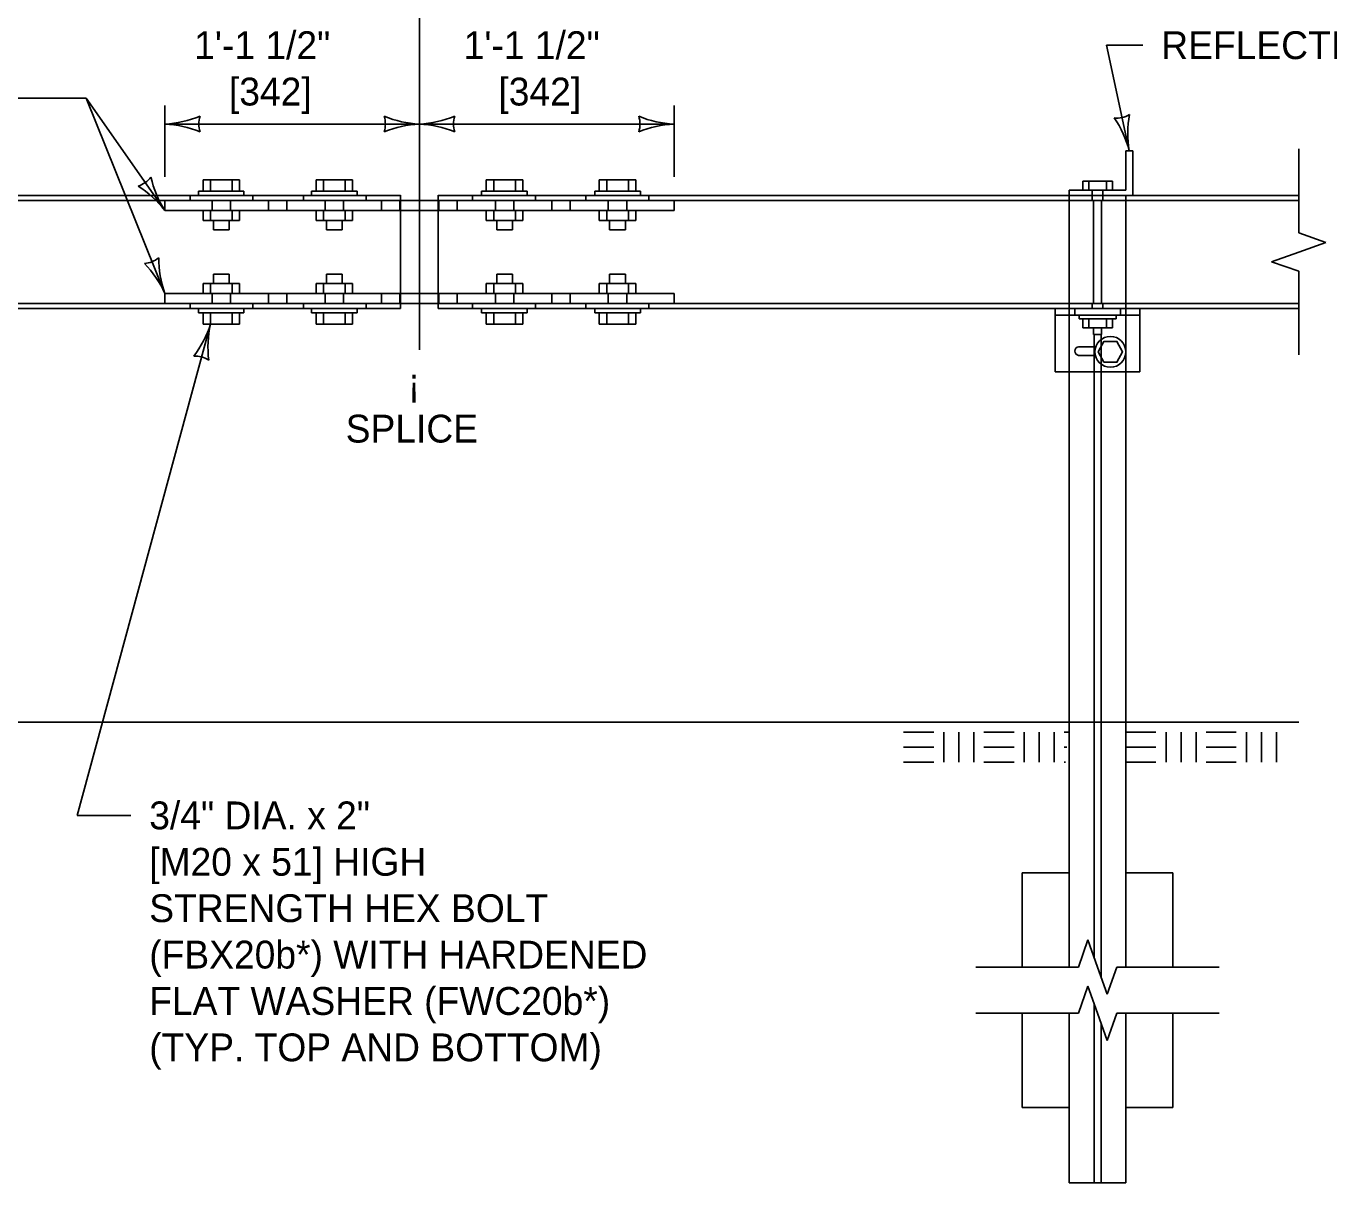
# Model space of a CAD drawing. Extents: x 49991.4 to 50021, y 49987.6 to 50011.4.
# Drawn here: x 50012.323 to 50015.133, y 50004.402 to 50006.896 of the extents above; entities that cross this region are included whole.
import ezdxf

# ---------------------------------------------------------------- set-up
doc = ezdxf.new("R2010")
doc.units = 0
for name, color, linetype in [('Level 1', 7, 'Continuous'), ('Level 2', 7, 'Continuous'), ('Level 3', 7, 'Continuous'), ('Level 4', 7, 'Continuous'), ('Level 5', 7, 'Continuous'), ('Level 6', 7, 'Continuous')]:
    doc.layers.add(name, color=color, linetype=linetype)

msp = doc.modelspace()

# ---------------------------------------------------------------- linework, layer by layer
at = {"layer": 'Level 1'}
for p, q in [((50014.695, 50006.5419), (50014.695, 50006.627)), ((50014.695, 50006.627), (50014.7102, 50006.627)), ((50014.7102, 50006.5309), (50014.7102, 50006.627)), ((50012.7049, 50006.5402), (50012.7049, 50006.5646)), ((50012.7049, 50006.5646), (50012.7838, 50006.5646)), ((50012.721, 50006.5402), (50012.721, 50006.5646)), ((50012.7677, 50006.5402), (50012.7677, 50006.5646)), ((50012.7838, 50006.5402), (50012.7838, 50006.5646)), ((50012.9486, 50006.5402), (50012.9486, 50006.5646)), ((50012.9486, 50006.5646), (50013.0274, 50006.5646)), ((50012.9646, 50006.5402), (50012.9646, 50006.5646)), ((50013.0114, 50006.5402), (50013.0114, 50006.5646)), ((50013.0274, 50006.5402), (50013.0274, 50006.5646)), ((50013.3158, 50006.5402), (50013.3158, 50006.5646)), ((50013.3946, 50006.5646), (50013.3158, 50006.5646)), ((50013.3318, 50006.5402), (50013.3318, 50006.5646)), ((50013.3786, 50006.5402), (50013.3786, 50006.5646)), ((50013.3946, 50006.5402), (50013.3946, 50006.5646)), ((50013.5594, 50006.5402), (50013.5594, 50006.5646)), ((50013.6383, 50006.5646), (50013.5594, 50006.5646)), ((50013.5755, 50006.5402), (50013.5755, 50006.5646)), ((50013.6222, 50006.5402), (50013.6222, 50006.5646)), ((50013.6383, 50006.5402), (50013.6383, 50006.5646)), ((50014.6026, 50006.5419), (50014.6026, 50006.5616)), ((50014.6026, 50006.5616), (50014.6665, 50006.5616)), ((50014.6156, 50006.5419), (50014.6156, 50006.5616)), ((50014.6534, 50006.5419), (50014.6534, 50006.5616)), ((50014.6665, 50006.5419), (50014.6665, 50006.5616)), ((50010.9506, 50006.5309), (50013.131, 50006.5309)), ((50012.6948, 50006.5402), (50012.7932, 50006.5402)), ((50012.6948, 50006.5309), (50012.6948, 50006.5402)), ((50012.7932, 50006.5309), (50012.7932, 50006.5402)), ((50012.9392, 50006.5402), (50013.0375, 50006.5402)), ((50012.9392, 50006.5309), (50012.9392, 50006.5402)), ((50013.0375, 50006.5309), (50013.0375, 50006.5402)), ((50013.131, 50006.287), (50013.131, 50006.5316)), ((50013.131, 50006.5198), (50013.2122, 50006.5198)), ((50013.1602, 50006.5199), (50013.183, 50006.5199)), ((50013.2122, 50006.287), (50013.2122, 50006.5316)), ((50013.2122, 50006.5309), (50015.0681, 50006.5309)), ((50013.404, 50006.5402), (50013.3057, 50006.5402)), ((50013.3057, 50006.5309), (50013.3057, 50006.5402)), ((50013.404, 50006.5309), (50013.404, 50006.5402)), ((50013.6484, 50006.5402), (50013.55, 50006.5402)), ((50013.55, 50006.5309), (50013.55, 50006.5402)), ((50013.6484, 50006.5309), (50013.6484, 50006.5402)), ((50014.5732, 50006.5309), (50014.5732, 50006.5419)), ((50014.5732, 50006.5419), (50014.695, 50006.5419)), ((50013.131, 50006.4983), (50013.2122, 50006.4983)), ((50013.131, 50006.3197), (50013.2122, 50006.3197)), ((50013.131, 50006.2981), (50013.2122, 50006.2981)), ((50013.1602, 50006.2981), (50013.183, 50006.2981)), ((50010.9506, 50006.287), (50013.131, 50006.287)), ((50012.6948, 50006.2871), (50012.6948, 50006.2778)), ((50012.6948, 50006.2778), (50012.7932, 50006.2778)), ((50012.7049, 50006.2778), (50012.7049, 50006.2534)), ((50012.721, 50006.2778), (50012.721, 50006.2534)), ((50012.7677, 50006.2778), (50012.7677, 50006.2534)), ((50012.7838, 50006.2778), (50012.7838, 50006.2534)), ((50012.7932, 50006.2871), (50012.7932, 50006.2778)), ((50012.9392, 50006.2871), (50012.9392, 50006.2778)), ((50012.9392, 50006.2778), (50013.0375, 50006.2778)), ((50012.9486, 50006.2778), (50012.9486, 50006.2534)), ((50012.9646, 50006.2778), (50012.9646, 50006.2534)), ((50013.0114, 50006.2778), (50013.0114, 50006.2534)), ((50013.0274, 50006.2778), (50013.0274, 50006.2534)), ((50013.0375, 50006.2871), (50013.0375, 50006.2778)), ((50013.2122, 50006.287), (50015.0681, 50006.287)), ((50013.3057, 50006.2871), (50013.3057, 50006.2778)), ((50013.404, 50006.2778), (50013.3057, 50006.2778)), ((50013.3158, 50006.2778), (50013.3158, 50006.2534)), ((50013.3318, 50006.2778), (50013.3318, 50006.2534)), ((50013.3786, 50006.2778), (50013.3786, 50006.2534)), ((50013.3946, 50006.2778), (50013.3946, 50006.2534)), ((50013.404, 50006.2871), (50013.404, 50006.2778)), ((50013.55, 50006.2871), (50013.55, 50006.2778)), ((50013.6484, 50006.2778), (50013.55, 50006.2778)), ((50013.5594, 50006.2778), (50013.5594, 50006.2534)), ((50013.5755, 50006.2778), (50013.5755, 50006.2534)), ((50013.6222, 50006.2778), (50013.6222, 50006.2534)), ((50013.6383, 50006.2778), (50013.6383, 50006.2534)), ((50013.6484, 50006.2871), (50013.6484, 50006.2778)), ((50014.5427, 50006.1508), (50014.5427, 50006.287)), ((50014.5427, 50006.2724), (50014.7256, 50006.2724)), ((50014.5943, 50006.2724), (50014.5943, 50006.2649)), ((50014.5943, 50006.2649), (50014.6741, 50006.2649)), ((50014.6026, 50006.2649), (50014.6026, 50006.2452)), ((50014.6156, 50006.2649), (50014.6156, 50006.2452)), ((50014.6534, 50006.2649), (50014.6534, 50006.2452)), ((50014.6665, 50006.2649), (50014.6665, 50006.2452)), ((50014.6741, 50006.2724), (50014.6741, 50006.2649)), ((50014.7256, 50006.1508), (50014.7256, 50006.287)), ((50012.7049, 50006.2534), (50012.7838, 50006.2534)), ((50012.9486, 50006.2534), (50013.0274, 50006.2534)), ((50013.3946, 50006.2534), (50013.3158, 50006.2534)), ((50013.6383, 50006.2534), (50013.5594, 50006.2534)), ((50014.6026, 50006.2452), (50014.6665, 50006.2452)), ((50014.5931, 50006.2045), (50014.6303, 50006.2045)), ((50014.5931, 50006.1859), (50014.6294, 50006.1859)), ((50014.5427, 50006.1508), (50014.7256, 50006.1508)), ((50014.5732, 50005.3957), (50014.5732, 50006.1508)), ((50014.695, 50005.3957), (50014.695, 50006.1508)), ((50015.0681, 50005.3957), (50010.756, 50005.3957)), ((50014.2157, 50005.3741), (50014.2807, 50005.3741)), ((50014.3024, 50005.3091), (50014.3024, 50005.3741)), ((50014.3349, 50005.3091), (50014.3349, 50005.3741)), ((50014.3674, 50005.3091), (50014.3674, 50005.3741)), ((50014.389, 50005.3741), (50014.4541, 50005.3741)), ((50014.4758, 50005.3091), (50014.4758, 50005.3741)), ((50014.5082, 50005.3091), (50014.5082, 50005.3741)), ((50014.5407, 50005.3091), (50014.5407, 50005.3741)), ((50014.6951, 50005.3741), (50014.6951, 50005.3741)), ((50014.6951, 50005.3741), (50014.7601, 50005.3741)), ((50014.7818, 50005.3091), (50014.7818, 50005.3741)), ((50014.8143, 50005.3091), (50014.8143, 50005.3741)), ((50014.8468, 50005.3091), (50014.8468, 50005.3741)), ((50014.8685, 50005.3741), (50014.9334, 50005.3741)), ((50014.9551, 50005.3091), (50014.9551, 50005.3741)), ((50014.9877, 50005.3091), (50014.9877, 50005.3741)), ((50015.0202, 50005.3091), (50015.0202, 50005.3741)), ((50014.2157, 50005.3416), (50014.2807, 50005.3416)), ((50014.389, 50005.3416), (50014.4541, 50005.3416)), ((50014.6951, 50005.3416), (50014.7601, 50005.3416)), ((50014.8685, 50005.3416), (50014.9334, 50005.3416)), ((50014.2157, 50005.3091), (50014.2807, 50005.3091)), ((50014.389, 50005.3091), (50014.4541, 50005.3091)), ((50014.6951, 50005.3091), (50014.7601, 50005.3091)), ((50014.8685, 50005.3091), (50014.9334, 50005.3091))]:
    msp.add_line(p, q, dxfattribs=at)
for points in [[(50014.6257, 50006.2452), (50014.6257, 50006.231)], [(50014.6426, 50006.2452), (50014.6426, 50006.231)], [(50014.6257, 50006.231), (50014.6426, 50006.231)], [(50014.5732, 50005.3957), (50014.5732, 50005.3957)], [(50014.6951, 50005.3957), (50014.6951, 50005.3957)], [(50014.5624, 50005.3741), (50014.5713, 50005.3741)], [(50014.5624, 50005.3416), (50014.5682, 50005.3416)], [(50014.5624, 50005.3091), (50014.5652, 50005.3091)]]:
    msp.add_lwpolyline(points, dxfattribs=at)
msp.add_lwpolyline([(50014.6477, 50006.1713), (50014.6758, 50006.1713), (50014.6881, 50006.1936), (50014.6758, 50006.2161), (50014.6477, 50006.2161), (50014.6354, 50006.1936)], close=True, dxfattribs=at)
msp.add_circle((50014.6618, 50006.1936), 0.0333, dxfattribs=at)
msp.add_arc((50014.5945, 50006.1952), 0.00938, 98.5498, 261.4502, dxfattribs=at)
at = {"layer": 'Level 3'}
for p, q in [((50012.4337, 50005.1944), (50012.721, 50006.2534)), ((50012.5489, 50005.1944), (50012.4337, 50005.1944))]:
    msp.add_line(p, q, dxfattribs=at)
for points in [[(50014.6532, 50006.8546), (50014.7026, 50006.627)], [(50014.6532, 50006.8546), (50014.7315, 50006.8546)], [(50012.1682, 50006.7406), (50012.4527, 50006.7406)], [(50012.3555, 50006.7406), (50012.4527, 50006.7406)], [(50012.6225, 50006.4983), (50012.4527, 50006.7406)], [(50012.6225, 50006.3197), (50012.4527, 50006.7406)], [(50012.6225, 50006.4983), (50012.4527, 50006.7406)], [(50012.6225, 50006.3197), (50012.4527, 50006.7406)], [(50012.6225, 50006.4983), (50012.4527, 50006.7406)], [(50012.6225, 50006.3197), (50012.4527, 50006.7406)], [(50012.6225, 50006.7246), (50012.6225, 50006.5709)], [(50013.7207, 50006.7246), (50013.7208, 50006.5709)], [(50012.6225, 50006.6846), (50013.1716, 50006.6846)], [(50013.1716, 50006.6846), (50013.7207, 50006.6846)]]:
    msp.add_lwpolyline(points, dxfattribs=at)
for centre, radius, start, end in [((50012.611, 50006.9173), 0.233, 272.8273, 292.0772), ((50012.6134, 50006.4625), 0.2223, 67.456, 87.6395), ((50012.7507, 50006.6846), 0.0548, 162.1388, 197.8612), ((50013.1808, 50006.9067), 0.2223, 247.456, 267.6395), ((50013.0434, 50006.6846), 0.0548, 342.1388, 17.8612), ((50013.1831, 50006.4519), 0.233, 92.8273, 112.0772), ((50013.1601, 50006.9173), 0.233, 272.8273, 292.0772), ((50013.1624, 50006.4625), 0.2223, 67.456, 87.6395), ((50013.2998, 50006.6846), 0.0548, 162.1388, 197.8612), ((50013.7299, 50006.9067), 0.2223, 247.456, 267.6395), ((50013.5925, 50006.6846), 0.0548, 342.1388, 17.8612), ((50013.7322, 50006.4519), 0.233, 92.8273, 112.0772), ((50014.6754, 50006.7523), 0.0548, 264.379, 300.1014), ((50014.4776, 50006.5664), 0.233, 15.0675, 34.3174), ((50014.9216, 50006.6651), 0.2223, 169.6962, 189.8797), ((50012.5489, 50006.6033), 0.0548, 287.161, 322.8833), ((50012.5489, 50006.6033), 0.0548, 287.161, 322.8833), ((50012.4385, 50006.3553), 0.233, 37.8495, 57.0993), ((50012.4385, 50006.3553), 0.233, 37.8495, 57.0993), ((50012.8097, 50006.6183), 0.2223, 192.4782, 212.6617), ((50012.8097, 50006.6183), 0.2223, 192.4782, 212.6617), ((50012.5745, 50006.4386), 0.0548, 274.109, 309.8314), ((50012.5745, 50006.4386), 0.0548, 274.109, 309.8314), ((50012.411, 50006.222), 0.233, 24.7975, 44.0474), ((50012.411, 50006.222), 0.233, 24.7975, 44.0474), ((50012.8319, 50006.3943), 0.2223, 179.4262, 199.6097), ((50012.8319, 50006.3943), 0.2223, 179.4262, 199.6097), ((50012.509, 50006.3204), 0.2223, 322.2773, 342.4608), ((50012.9486, 50006.2036), 0.233, 167.6486, 186.8984), ((50012.6874, 50006.1297), 0.0548, 56.9601, 92.6824)]:
    msp.add_arc(centre, radius, start, end, dxfattribs=at)
at = {"layer": 'Level 4'}
for p, q in [((50010.9506, 50006.5198), (50013.131, 50006.5198)), ((50012.6225, 50006.4983), (50012.6225, 50006.5199)), ((50012.7246, 50006.4983), (50012.7246, 50006.5199)), ((50012.7642, 50006.4983), (50012.7642, 50006.5199)), ((50012.8464, 50006.4983), (50012.8464, 50006.5199)), ((50012.886, 50006.4983), (50012.886, 50006.5199)), ((50012.9682, 50006.4983), (50012.9682, 50006.5199)), ((50013.0078, 50006.4983), (50013.0078, 50006.5199)), ((50013.09, 50006.4983), (50013.09, 50006.5199)), ((50013.1296, 50006.4983), (50013.1296, 50006.5199)), ((50013.2122, 50006.5198), (50015.0681, 50006.5198)), ((50013.2136, 50006.4983), (50013.2136, 50006.5199)), ((50013.2532, 50006.4983), (50013.2532, 50006.5199)), ((50013.3354, 50006.4983), (50013.3354, 50006.5199)), ((50013.375, 50006.4983), (50013.375, 50006.5199)), ((50013.4572, 50006.4983), (50013.4572, 50006.5199)), ((50013.4968, 50006.4983), (50013.4968, 50006.5199)), ((50013.579, 50006.4983), (50013.579, 50006.5199)), ((50013.6186, 50006.4983), (50013.6186, 50006.5199)), ((50013.7207, 50006.4983), (50013.7207, 50006.5199)), ((50014.5732, 50006.1508), (50014.5732, 50006.5309)), ((50014.6228, 50006.5198), (50014.6228, 50006.5419)), ((50014.6257, 50006.2981), (50014.6257, 50006.5198)), ((50014.6426, 50006.2981), (50014.6426, 50006.5198)), ((50014.6454, 50006.5198), (50014.6454, 50006.5419)), ((50014.695, 50006.1508), (50014.695, 50006.5309)), ((50013.131, 50006.4983), (50012.6225, 50006.4983)), ((50012.7049, 50006.4769), (50012.7049, 50006.4983)), ((50012.721, 50006.4769), (50012.721, 50006.4983)), ((50012.7677, 50006.4769), (50012.7677, 50006.4983)), ((50012.7838, 50006.4769), (50012.7838, 50006.4983)), ((50012.9486, 50006.4769), (50012.9486, 50006.4983)), ((50012.9646, 50006.4769), (50012.9646, 50006.4983)), ((50013.0114, 50006.4769), (50013.0114, 50006.4983)), ((50013.0274, 50006.4769), (50013.0274, 50006.4983)), ((50013.2122, 50006.4983), (50013.7207, 50006.4983)), ((50013.3158, 50006.4769), (50013.3158, 50006.4983)), ((50013.3318, 50006.4769), (50013.3318, 50006.4983)), ((50013.3786, 50006.4769), (50013.3786, 50006.4983)), ((50013.3946, 50006.4769), (50013.3946, 50006.4983)), ((50013.5594, 50006.4769), (50013.5594, 50006.4983)), ((50013.5755, 50006.4769), (50013.5755, 50006.4983)), ((50013.6222, 50006.4769), (50013.6222, 50006.4983)), ((50013.6383, 50006.4769), (50013.6383, 50006.4983)), ((50012.7049, 50006.4769), (50012.7838, 50006.4769)), ((50012.7274, 50006.4568), (50012.7274, 50006.4769)), ((50012.7614, 50006.4568), (50012.7614, 50006.4769)), ((50012.9486, 50006.4769), (50013.0274, 50006.4769)), ((50012.971, 50006.4568), (50012.971, 50006.4769)), ((50013.005, 50006.4568), (50013.005, 50006.4769)), ((50013.3946, 50006.4769), (50013.3158, 50006.4769)), ((50013.3382, 50006.4568), (50013.3382, 50006.4769)), ((50013.3722, 50006.4568), (50013.3722, 50006.4769)), ((50013.6383, 50006.4769), (50013.5594, 50006.4769)), ((50013.5818, 50006.4568), (50013.5818, 50006.4769)), ((50013.6158, 50006.4568), (50013.6158, 50006.4769)), ((50012.7274, 50006.4568), (50012.7614, 50006.4568)), ((50013.0049, 50006.4568), (50012.971, 50006.4568)), ((50013.3383, 50006.4568), (50013.3722, 50006.4568)), ((50013.6158, 50006.4568), (50013.5818, 50006.4568)), ((50012.7274, 50006.3613), (50012.7274, 50006.3412)), ((50012.7274, 50006.3613), (50012.7614, 50006.3613)), ((50012.7614, 50006.3613), (50012.7614, 50006.3412)), ((50012.971, 50006.3613), (50012.971, 50006.3412)), ((50013.0049, 50006.3613), (50012.971, 50006.3613)), ((50013.005, 50006.3613), (50013.005, 50006.3412)), ((50013.3382, 50006.3613), (50013.3382, 50006.3412)), ((50013.3383, 50006.3613), (50013.3722, 50006.3613)), ((50013.3722, 50006.3613), (50013.3722, 50006.3412)), ((50013.5818, 50006.3613), (50013.5818, 50006.3412)), ((50013.6158, 50006.3613), (50013.5818, 50006.3613)), ((50013.6158, 50006.3613), (50013.6158, 50006.3412)), ((50013.131, 50006.3197), (50012.6225, 50006.3197)), ((50012.6225, 50006.3197), (50012.6225, 50006.2981)), ((50012.7049, 50006.3412), (50012.7049, 50006.3197)), ((50012.7049, 50006.3412), (50012.7838, 50006.3412)), ((50012.721, 50006.3412), (50012.721, 50006.3197)), ((50012.7246, 50006.3197), (50012.7246, 50006.2981)), ((50012.7642, 50006.3197), (50012.7642, 50006.2981)), ((50012.7677, 50006.3412), (50012.7677, 50006.3197)), ((50012.7838, 50006.3412), (50012.7838, 50006.3197)), ((50012.8464, 50006.3197), (50012.8464, 50006.2981)), ((50012.886, 50006.3197), (50012.886, 50006.2981)), ((50012.9486, 50006.3412), (50012.9486, 50006.3197)), ((50012.9486, 50006.3412), (50013.0274, 50006.3412)), ((50012.9646, 50006.3412), (50012.9646, 50006.3197)), ((50012.9682, 50006.3197), (50012.9682, 50006.2981)), ((50013.0078, 50006.3197), (50013.0078, 50006.2981)), ((50013.0114, 50006.3412), (50013.0114, 50006.3197)), ((50013.0274, 50006.3412), (50013.0274, 50006.3197)), ((50013.09, 50006.3197), (50013.09, 50006.2981)), ((50013.1296, 50006.3197), (50013.1296, 50006.2981)), ((50013.2122, 50006.3197), (50013.7207, 50006.3197)), ((50013.2136, 50006.3197), (50013.2136, 50006.2981)), ((50013.2532, 50006.3197), (50013.2532, 50006.2981)), ((50013.3158, 50006.3412), (50013.3158, 50006.3197)), ((50013.3946, 50006.3412), (50013.3158, 50006.3412)), ((50013.3318, 50006.3412), (50013.3318, 50006.3197)), ((50013.3354, 50006.3197), (50013.3354, 50006.2981)), ((50013.375, 50006.3197), (50013.375, 50006.2981)), ((50013.3786, 50006.3412), (50013.3786, 50006.3197)), ((50013.3946, 50006.3412), (50013.3946, 50006.3197)), ((50013.4572, 50006.3197), (50013.4572, 50006.2981)), ((50013.4968, 50006.3197), (50013.4968, 50006.2981)), ((50013.5594, 50006.3412), (50013.5594, 50006.3197)), ((50013.6383, 50006.3412), (50013.5594, 50006.3412)), ((50013.5755, 50006.3412), (50013.5755, 50006.3197)), ((50013.579, 50006.3197), (50013.579, 50006.2981)), ((50013.6186, 50006.3197), (50013.6186, 50006.2981)), ((50013.6222, 50006.3412), (50013.6222, 50006.3197)), ((50013.6383, 50006.3412), (50013.6383, 50006.3197)), ((50013.7207, 50006.3197), (50013.7207, 50006.2981)), ((50010.9506, 50006.2981), (50013.131, 50006.2981)), ((50013.2122, 50006.2981), (50015.0681, 50006.2981)), ((50014.6228, 50006.287), (50014.6228, 50006.2981)), ((50014.6454, 50006.287), (50014.6454, 50006.2981)), ((50014.5851, 50006.2724), (50014.5851, 50006.287)), ((50014.6838, 50006.2724), (50014.6838, 50006.287)), ((50014.6266, 50004.889), (50014.6266, 50006.231)), ((50014.6418, 50004.8461), (50014.6418, 50006.231)), ((50014.5732, 50005.3957), (50014.5732, 50004.8676)), ((50014.6951, 50005.3957), (50014.6951, 50004.8676)), ((50014.4717, 50005.0708), (50014.5732, 50005.0708)), ((50014.4717, 50005.0708), (50014.4717, 50004.8676)), ((50014.6951, 50005.0708), (50014.7966, 50005.0708)), ((50014.7966, 50005.0708), (50014.7966, 50004.8676)), ((50014.6266, 50004.4022), (50014.6266, 50004.7893)), ((50014.4717, 50004.7678), (50014.4717, 50004.5647)), ((50014.5732, 50004.7678), (50014.5732, 50004.4022)), ((50014.6418, 50004.4022), (50014.6418, 50004.7464)), ((50014.6951, 50004.7678), (50014.6951, 50004.4022)), ((50014.7966, 50004.7678), (50014.7966, 50004.5647)), ((50014.4717, 50004.5647), (50014.5732, 50004.5647)), ((50014.6951, 50004.5647), (50014.7966, 50004.5647)), ((50014.5732, 50004.4022), (50014.6951, 50004.4022))]:
    msp.add_line(p, q, dxfattribs=at)
for points in [[(50012.677, 50006.5199), (50012.677, 50006.5309)], [(50012.8126, 50006.5199), (50012.8126, 50006.5309)], [(50012.9213, 50006.5199), (50012.9213, 50006.5309)], [(50013.057, 50006.5199), (50013.057, 50006.5309)], [(50013.2862, 50006.5199), (50013.2862, 50006.5309)], [(50013.4219, 50006.5199), (50013.4219, 50006.5309)], [(50013.5306, 50006.5199), (50013.5306, 50006.5309)], [(50013.6662, 50006.5199), (50013.6662, 50006.5309)], [(50012.677, 50006.2981), (50012.677, 50006.2871)], [(50012.8126, 50006.2981), (50012.8126, 50006.2871)], [(50012.9213, 50006.2981), (50012.9213, 50006.2871)], [(50013.057, 50006.2981), (50013.057, 50006.2871)], [(50013.2862, 50006.2981), (50013.2862, 50006.2871)], [(50013.4219, 50006.2981), (50013.4219, 50006.2871)], [(50013.5306, 50006.2981), (50013.5306, 50006.2871)], [(50013.6662, 50006.2981), (50013.6662, 50006.2871)]]:
    msp.add_lwpolyline(points, dxfattribs=at)
at = {"layer": 'Level 5'}
msp.add_lwpolyline([(50013.1716, 50007.7118), (50013.1716, 50006.1981)], dxfattribs=at)
at = {"layer": 'Level 6'}
for p, q in [((50015.0681, 50006.6309), (50015.0681, 50006.4501)), ((50015.1266, 50006.4293), (50015.0681, 50006.4501)), ((50015.0681, 50006.4086), (50015.0096, 50006.3879)), ((50015.1266, 50006.4293), (50015.0681, 50006.4086)), ((50015.0681, 50006.3672), (50015.0096, 50006.3879)), ((50015.0681, 50006.3672), (50015.0681, 50006.187)), ((50014.6134, 50004.9261), (50014.5927, 50004.8676)), ((50014.6134, 50004.9261), (50014.6342, 50004.8676)), ((50014.3717, 50004.8676), (50014.5927, 50004.8676)), ((50014.6342, 50004.8676), (50014.6549, 50004.8091)), ((50014.6756, 50004.8676), (50014.6549, 50004.8091)), ((50014.6756, 50004.8676), (50014.8966, 50004.8676)), ((50014.6134, 50004.8263), (50014.5927, 50004.7678)), ((50014.6134, 50004.8263), (50014.6342, 50004.7678)), ((50014.5927, 50004.7678), (50014.3717, 50004.7678)), ((50014.6342, 50004.7678), (50014.6549, 50004.7093)), ((50014.6756, 50004.7678), (50014.6549, 50004.7093)), ((50014.8966, 50004.7678), (50014.6756, 50004.7678))]:
    msp.add_line(p, q, dxfattribs=at)

# ---------------------------------------------------------------- texts
at = {"layer": 'Level 2'}
for s, p in [('1\'-1 1/2"', (50012.6858, 50006.8246)), ('1\'-1 1/2"', (50013.267, 50006.8246)), ('REFLECTIVE TAB', (50014.7715, 50006.8246)), ('[342]', (50012.7608, 50006.7246)), ('[342]', (50013.342, 50006.7246)), ('¡', (50013.1465, 50006.0981)), ('SPLICE', (50013.0126, 50005.9981)), ('3/4" DIA. x 2" ', (50012.5889, 50005.1644)), ('[M20 x 51] HIGH', (50012.5889, 50005.0644)), ('STRENGTH HEX BOLT', (50012.5889, 50004.9644)), ('(FBX20b*) WITH HARDENED', (50012.5889, 50004.8644)), ('FLAT WASHER (FWC20b*)', (50012.5889, 50004.7644)), ('(TYP. TOP AND BOTTOM)', (50012.5889, 50004.6644))]:
    msp.add_text(s, height=0.06, dxfattribs=at).set_placement(p)

doc.saveas('drawing.dxf')
